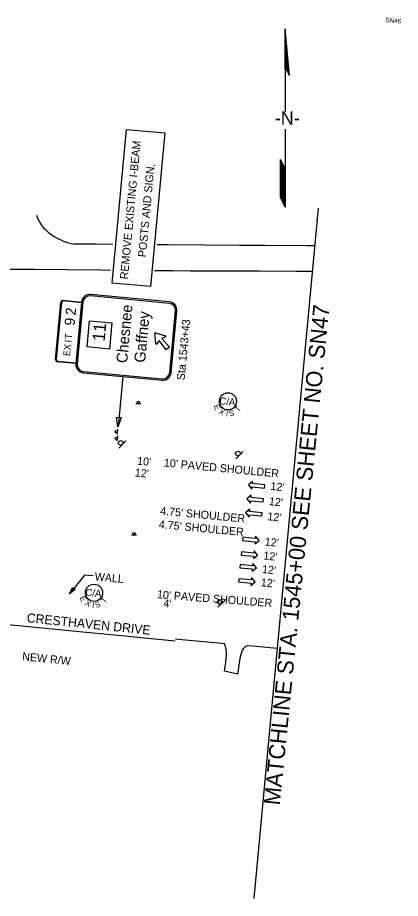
# Model space of a CAD drawing. Extents: x 1800374 to 1802004, y 1187708 to 1188617.
# Drawn here: x 1801669 to 1802004, y 1187708 to 1188479 of the extents above; entities that cross this region are included whole.
import ezdxf

# ---------------------------------------------------------------- set-up
doc = ezdxf.new("R2010")
doc.units = 0
for name, color, linetype in [('RD_EX_Road', 7, 'Continuous'), ('RD_PD_Final_LnLine', 7, 'Continuous'), ('RD_PD_Final_TX', 7, 'Continuous'), ('RD_PD_RW_TX', 7, 'Continuous'), ('RD_SHT_MatchLine', 7, 'Continuous'), ('RD_SHT_TX', 7, 'Continuous'), ('RD_Sketch1', 7, 'Continuous'), ('RD_Sketch8', 7, 'Continuous'), ('RD_TX_RoadID', 7, 'Continuous'), ('SN_P_Signs', 7, 'Continuous'), ('TERMINATOR', 7, 'Continuous')]:
    doc.layers.add(name, color=color, linetype=linetype)

# ---------------------------------------------------------------- blocks, each defined once
blk = doc.blocks.new('SARRW2')
at = {"layer": 'RD_PD_Final_LnLine'}
blk.add_lwpolyline([(-12, 1.2), (-12, -1.2), (-2.83, -1.2), (-2.83, -2.83), (0, 0), (-2.83, 2.83), (-2.83, 1.2)], close=True, dxfattribs=at)

msp = doc.modelspace()

# ---------------------------------------------------------------- linework, layer by layer
at = {"layer": 'RD_EX_Road'}
for points in [[(1801685.48, 1188305.79), (1801685.97, 1188304.34), (1801687.07, 1188301.79), (1801688.39, 1188299.35), (1801689.91, 1188297.02), (1801691.62, 1188294.84), (1801693.51, 1188292.81), (1801695.57, 1188290.95), (1801695.73, 1188290.82), (1801698.56, 1188288.7), (1801701.52, 1188286.79), (1801704.61, 1188285.07), (1801707.81, 1188283.57), (1801708.38, 1188283.32), (1801710.8, 1188282.35), (1801713.29, 1188281.6), (1801715.83, 1188281.08), (1801718.42, 1188280.79), (1801719.35, 1188280.74), (1801736.78, 1188280.71), (1801752.34, 1188280.54)], [(1801791.08, 1188280.16), (1801800.88, 1188280.08), (1801833.37, 1188279.84), (1801863.33, 1188279.56), (1801885.57, 1188279.5), (1801922.18, 1188279.21), (1801929.09, 1188279.22)], [(1801750.18, 1188257.47), (1801742.16, 1188257.54), (1801712.17, 1188257.84), (1801684.43, 1188258.15), (1801653.76, 1188258.34), (1801623.47, 1188258.55), (1801596.82, 1188258.7), (1801565.74, 1188258.88), (1801534.34, 1188259.2), (1801510.07, 1188259.36), (1801485.44, 1188259.54), (1801465.11, 1188259.51), (1801443.43, 1188259.67), (1801423.7, 1188259.6), (1801400.14, 1188259.52), (1801374.88, 1188259.49), (1801351.57, 1188259.44), (1801326.73, 1188259.43), (1801300.32, 1188259.52), (1801276.46, 1188259.35), (1801254.13, 1188259.2), (1801227.4, 1188259.14), (1801201, 1188258.95), (1801190.24, 1188258.95)], [(1801926.95, 1188256.38), (1801912.81, 1188256.45), (1801880.86, 1188256.7), (1801851.61, 1188256.8), (1801820.08, 1188256.94), (1801804.92, 1188257.1), (1801789.17, 1188257.21), (1801788.94, 1188257.21)], [(1801807.01, 1187933.22), (1801786, 1187935.24), (1801756.86, 1187938.09), (1801731.9, 1187940.55), (1801708.11, 1187942.83), (1801675.84, 1187945.99), (1801644.76, 1187948.86)], [(1801896.11, 1187926.73), (1801874.92, 1187928.81), (1801869.81, 1187929.15), (1801868.54, 1187928.39), (1801867.4, 1187927.44), (1801866.44, 1187926.32), (1801865.66, 1187925.06), (1801865.09, 1187923.69), (1801864.98, 1187923.33), (1801864.23, 1187920.71), (1801863.47, 1187918.08), (1801861.44, 1187904.4), (1801861.43, 1187904.32), (1801850.02, 1187906.92), (1801851.17, 1187914.64), (1801851.96, 1187920.9), (1801851.89, 1187923.45), (1801851.58, 1187925.99), (1801850.25, 1187930.85), (1801847.96, 1187931.07), (1801815.91, 1187934.08), (1801807.16, 1187934.81)]]:
    msp.add_lwpolyline(points, dxfattribs=at)
at = {"layer": 'RD_PD_Final_TX'}
for p, q in [((1801727.55, 1187990.9), (1801714.38, 1187974.42)), ((1801734.96, 1187990.21), (1801727.55, 1187990.9))]:
    msp.add_line(p, q, dxfattribs=at)
at = {"layer": 'RD_SHT_MatchLine'}
msp.add_line((1801932.15, 1188311.91), (1801875.67, 1187708.14), dxfattribs=at)
at = {"layer": 'RD_Sketch1'}
for p, q in [((1801903.25, 1188468.74), (1801903.04, 1188433.57)), ((1801906.98, 1188428.03), (1801903.25, 1188468.74)), ((1801903.55, 1188434.98), (1801906.98, 1188428.03)), ((1801903.25, 1188433.87), (1801903.25, 1188412.04)), ((1801903.25, 1188412.04), (1801903.25, 1188396.57)), ((1801903.25, 1188381.13), (1801903.25, 1188355.35)), ((1801899.26, 1188340.29), (1801899.26, 1188354.47)), ((1801899.26, 1188354.47), (1801903.25, 1188345.9)), ((1801903.25, 1188355.35), (1801903.25, 1188312.83)), ((1801899.26, 1188321.4), (1801899.26, 1188340.29)), ((1801903.25, 1188312.83), (1801899.26, 1188321.4))]:
    msp.add_line(p, q, dxfattribs=at)
for points in [[(1801903.26, 1188434.18), (1801903.26, 1188468.62)], [(1801903.36, 1188434.44), (1801903.36, 1188467.58)], [(1801903.45, 1188434.7), (1801903.45, 1188466.55)], [(1801903.55, 1188434.95), (1801903.55, 1188465.52)], [(1801903.64, 1188434.8), (1801903.64, 1188464.49)], [(1801903.74, 1188434.61), (1801903.74, 1188463.45)], [(1801903.83, 1188434.42), (1801903.83, 1188462.42)], [(1801903.92, 1188434.23), (1801903.92, 1188461.39)], [(1801904.02, 1188434.04), (1801904.02, 1188460.36)], [(1801904.11, 1188433.84), (1801904.11, 1188459.32)], [(1801904.21, 1188433.65), (1801904.21, 1188458.29)], [(1801903.17, 1188433.92), (1801903.17, 1188454.7)], [(1801904.3, 1188433.46), (1801904.3, 1188457.26)], [(1801904.4, 1188433.27), (1801904.4, 1188456.23)], [(1801904.49, 1188433.08), (1801904.49, 1188455.19)], [(1801904.59, 1188432.89), (1801904.59, 1188454.16)], [(1801904.68, 1188432.69), (1801904.68, 1188453.13)], [(1801904.77, 1188432.5), (1801904.77, 1188452.1)], [(1801904.87, 1188432.31), (1801904.87, 1188451.06)], [(1801904.96, 1188432.12), (1801904.96, 1188450.03)], [(1801905.06, 1188431.93), (1801905.06, 1188449)], [(1801905.15, 1188431.74), (1801905.15, 1188447.97)], [(1801905.25, 1188431.54), (1801905.25, 1188446.93)], [(1801905.34, 1188431.35), (1801905.34, 1188445.9)], [(1801905.44, 1188431.16), (1801905.44, 1188444.87)], [(1801905.53, 1188430.97), (1801905.53, 1188443.84)], [(1801905.62, 1188430.78), (1801905.62, 1188442.8)], [(1801903.07, 1188433.66), (1801903.07, 1188438.8)], [(1801905.72, 1188430.58), (1801905.72, 1188441.77)], [(1801905.81, 1188430.39), (1801905.81, 1188440.74)], [(1801905.91, 1188430.2), (1801905.91, 1188439.71)], [(1801906, 1188430.01), (1801906, 1188438.67)], [(1801906.1, 1188429.82), (1801906.1, 1188437.64)], [(1801906.19, 1188429.63), (1801906.19, 1188436.61)], [(1801906.29, 1188429.43), (1801906.29, 1188435.58)], [(1801906.38, 1188429.24), (1801906.38, 1188434.54)], [(1801906.48, 1188429.05), (1801906.48, 1188433.51)], [(1801906.57, 1188428.86), (1801906.57, 1188432.48)], [(1801906.66, 1188428.67), (1801906.66, 1188431.45)], [(1801906.76, 1188428.48), (1801906.76, 1188430.41)], [(1801906.85, 1188428.28), (1801906.85, 1188429.38)], [(1801906.95, 1188428.09), (1801906.95, 1188428.35)], [(1801899.34, 1188321.23), (1801899.34, 1188354.3)], [(1801899.43, 1188321.03), (1801899.43, 1188354.1)], [(1801899.52, 1188320.83), (1801899.52, 1188353.9)], [(1801899.62, 1188320.62), (1801899.62, 1188353.69)], [(1801899.71, 1188320.42), (1801899.71, 1188353.49)], [(1801899.81, 1188320.22), (1801899.81, 1188353.29)], [(1801899.9, 1188320.01), (1801899.9, 1188353.09)], [(1801900, 1188319.81), (1801900, 1188352.88)], [(1801900.09, 1188319.61), (1801900.09, 1188352.68)], [(1801900.19, 1188319.41), (1801900.19, 1188352.48)], [(1801900.28, 1188319.2), (1801900.28, 1188352.27)], [(1801900.37, 1188319), (1801900.37, 1188352.07)], [(1801900.47, 1188318.8), (1801900.47, 1188351.87)], [(1801900.56, 1188318.6), (1801900.56, 1188351.67)], [(1801900.66, 1188318.39), (1801900.66, 1188351.46)], [(1801900.75, 1188318.19), (1801900.75, 1188351.26)], [(1801900.85, 1188317.99), (1801900.85, 1188351.06)], [(1801900.94, 1188317.79), (1801900.94, 1188350.86)], [(1801901.04, 1188317.58), (1801901.04, 1188350.65)], [(1801901.13, 1188317.38), (1801901.13, 1188350.45)], [(1801901.22, 1188317.18), (1801901.22, 1188350.25)], [(1801901.32, 1188316.98), (1801901.32, 1188350.05)], [(1801901.41, 1188316.77), (1801901.41, 1188349.84)], [(1801901.51, 1188316.57), (1801901.51, 1188349.64)], [(1801901.6, 1188316.37), (1801901.6, 1188349.44)], [(1801901.7, 1188316.16), (1801901.7, 1188349.24)], [(1801901.79, 1188315.96), (1801901.79, 1188349.03)], [(1801901.89, 1188315.76), (1801901.89, 1188348.83)], [(1801901.98, 1188315.56), (1801901.98, 1188348.63)], [(1801902.08, 1188315.35), (1801902.08, 1188348.42)], [(1801902.17, 1188315.15), (1801902.17, 1188348.22)], [(1801902.26, 1188314.95), (1801902.26, 1188348.02)], [(1801902.36, 1188314.75), (1801902.36, 1188347.82)], [(1801902.45, 1188314.54), (1801902.45, 1188347.61)], [(1801902.55, 1188314.34), (1801902.55, 1188347.41)], [(1801902.64, 1188314.14), (1801902.64, 1188347.21)], [(1801902.74, 1188313.94), (1801902.74, 1188347.01)], [(1801902.83, 1188313.73), (1801902.83, 1188346.8)], [(1801902.93, 1188313.53), (1801902.93, 1188346.6)], [(1801903.02, 1188313.33), (1801903.02, 1188346.4)], [(1801903.11, 1188313.13), (1801903.11, 1188346.2)], [(1801903.21, 1188312.92), (1801903.21, 1188345.99)]]:
    msp.add_lwpolyline(points, dxfattribs=at)
at = {"layer": 'RD_Sketch8'}
for centre in [(1801853.07, 1188142.95), (1801735.87, 1187975.47)]:
    msp.add_circle(centre, 7.5, dxfattribs=at)
at = {"layer": 'SN_P_Signs'}
for p, q in [((1801751.74, 1188246.41), (1801764.32, 1188380.84)), ((1801764.32, 1188380.84), (1801797.79, 1188377.71)), ((1801797.79, 1188377.71), (1801785.21, 1188243.28)), ((1801785.21, 1188243.28), (1801751.74, 1188246.41)), ((1801801.82, 1188228.65), (1801732.71, 1188235.11)), ((1801731.89, 1188213.47), (1801751.49, 1188211.64)), ((1801751.49, 1188211.64), (1801749.34, 1188188.67)), ((1801749.34, 1188188.67), (1801729.74, 1188190.5)), ((1801726.54, 1188169.08), (1801795.64, 1188162.62)), ((1801760.98, 1188164.66), (1801756.86, 1188120.71)), ((1801772.37, 1188140.99), (1801776.87, 1188140.99)), ((1801756.16, 1188114.03), (1801756.57, 1188118.51)), ((1801756.25, 1188108.25), (1801756.67, 1188112.73)), ((1801757.43, 1188102.02), (1801763.79, 1188108.38)), ((1801860.09, 1188092.7), (1801866.45, 1188099.07)), ((1801768.55, 1188026.26), (1801773.05, 1188026.26)), ((1801844.29, 1187962.74), (1801850.65, 1187969.11))]:
    msp.add_line(p, q, dxfattribs=at)
for points in [[(1801801.93, 1188229.84), (1801732.83, 1188236.31)], [(1801702.2, 1188179.51), (1801706.9, 1188229.69)], [(1801707.49, 1188229.64), (1801702.8, 1188179.46)], [(1801724.93, 1188229.21), (1801708.8, 1188230.72)], [(1801708.86, 1188231.32), (1801724.99, 1188229.81), (1801724.93, 1188229.21)], [(1801724.99, 1188229.81), (1801719.93, 1188175.73)], [(1801726.18, 1188229.7), (1801721.12, 1188175.62)], [(1801802.17, 1188168.03), (1801807.23, 1188222.12)], [(1801803.37, 1188167.92), (1801808.43, 1188222)], [(1801729.74, 1188190.5), (1801731.89, 1188213.47)], [(1801790.02, 1188193.38), (1801789.11, 1188202.36)], [(1801789.68, 1188202.84), (1801798.34, 1188200.27)], [(1801793.01, 1188196.11), (1801790.83, 1188193.16)], [(1801801.85, 1188190.39), (1801799.08, 1188188.09), (1801793.01, 1188196.11)], [(1801798.4, 1188199.43), (1801795.09, 1188197.84)], [(1801795.09, 1188197.84), (1801801.85, 1188190.39)], [(1801703.88, 1188178.15), (1801720.01, 1188176.64), (1801719.96, 1188176.04), (1801703.83, 1188177.55)], [(1801726.42, 1188167.89), (1801795.53, 1188161.42)]]:
    msp.add_lwpolyline(points, dxfattribs=at)
msp.add_lwpolyline([(1801759.54, 1188128.72), (1801756.82, 1188120.72), (1801755.45, 1188129.06)], close=True, dxfattribs=at)
for centre, radius in [((1801774.63, 1188142), 1), ((1801755.36, 1188116.37), 1), ((1801755.45, 1188110.59), 1), ((1801759.19, 1188106.65), 2), ((1801861.85, 1188097.33), 2), ((1801770.81, 1188027.28), 1), ((1801846.05, 1187967.37), 2)]:
    msp.add_circle(centre, radius, dxfattribs=at)
for centre, radius, start, end in [((1801732.15, 1188229.14), 7.2, 84.65568, 174.65568), ((1801732.15, 1188229.14), 6, 84.65568, 174.65568), ((1801708.69, 1188229.53), 1.8, 84.65568, 174.65568), ((1801708.69, 1188229.53), 1.2, 84.65568, 174.65568), ((1801801.26, 1188222.67), 6, 354.65568, 84.65568), ((1801801.26, 1188222.67), 7.2, 354.65568, 84.65568), ((1801789.55, 1188202.4), 0.45, 73.47778, 185.83358), ((1801798.21, 1188199.84), 0.45, 295.69358, 73.47778), ((1801790.47, 1188193.42), 0.45, 185.83358, 323.61778), ((1801703.99, 1188179.35), 1.8, 174.65568, 264.65568), ((1801703.99, 1188179.35), 1.2, 174.65568, 264.65568), ((1801727.1, 1188175.06), 7.2, 174.65568, 264.65568), ((1801727.1, 1188175.06), 6, 174.65568, 264.65568), ((1801796.2, 1188168.59), 7.2, 264.65568, 354.65568), ((1801796.2, 1188168.59), 6, 264.65568, 354.65568)]:
    msp.add_arc(centre, radius, start, end, dxfattribs=at)
at = {"layer": 'TERMINATOR'}
msp.add_lwpolyline([(1801719.33, 1187978.23), (1801714.42, 1187974.48), (1801716.99, 1187980.11)], close=True, dxfattribs=at)

# ---------------------------------------------------------------- block references
at = {"layer": 'RD_PD_Final_LnLine'}
for p, xscale, yscale, rotation in [((1801870.99, 1188069.87), 1.1999999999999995, 1.200000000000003, 174.65567699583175), ((1801869.78, 1188057.65), 1.1999999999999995, 1.200000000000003, 174.65567699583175), ((1801868.57, 1188045.42), 1.1999999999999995, 1.200000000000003, 174.65567699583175), ((1801880.34, 1188021.23), 1.1999999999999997, 1.2000000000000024, -5.34432300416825), ((1801879.08, 1188008.51), 1.1999999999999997, 1.2000000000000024, -5.34432300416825), ((1801877.97, 1187997.4), 1.1999999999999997, 1.2000000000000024, -5.34432300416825), ((1801876.81, 1187985.02), 1.1999999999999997, 1.2000000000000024, -5.34432300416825)]:
    msp.add_blockref('SARRW2', p, dxfattribs=dict(at, xscale=xscale, yscale=yscale, rotation=rotation))

# ---------------------------------------------------------------- texts
at = {"layer": 'RD_PD_Final_TX'}
for s, rotation, p in [("10'", 354.76418, (1801773.34, 1188087.55)), ("10' PAVED SHOULDER", 354.54177, (1801796.75, 1188085.92)), ("12'", 354.76418, (1801771.36, 1188077.25)), ("12'", 354.02886, (1801890.03, 1188065.5)), ("12'", 353.95121, (1801888.72, 1188052.22)), ("4.75' SHOULDER", 354.65568, (1801793.53, 1188043.83)), ("12'", 354.02886, (1801887.41, 1188039.01)), ("4.75' SHOULDER", 354.65568, (1801792.32, 1188032.08)), ("12'", 353.95121, (1801885.07, 1188016.93)), ("12'", 353.95121, (1801883.85, 1188004.72)), ("12'", 353.95121, (1801882.67, 1187992.84)), ('WALL', 354.65568, (1801736.2, 1187986.35)), ("12'", 353.95121, (1801881.59, 1187981.26)), ("10' PAVED SHOULDER", 355.58396, (1801790.77, 1187970.72)), ("4'", 354.76418, (1801796.32, 1187962.93))]:
    msp.add_text(s, height=7, rotation=rotation, dxfattribs=at).set_placement(p)
at = {"layer": 'RD_PD_RW_TX'}
msp.add_text('NEW R/W', height=7, rotation=354.20316, dxfattribs=at).set_placement((1801672.68, 1187916.48))
at = {"layer": 'RD_SHT_TX'}
for s, height, rotation, p in [('SN46', 4, 354.65567, (1801990.82, 1188474.66)), ('MATCHLINE STA. 1545+00 SEE SHEET NO. SN47', 14.1726, 84.31294, (1801898.54, 1187789.14))]:
    msp.add_text(s, height=height, rotation=rotation, dxfattribs=at).set_placement(p)
at = {"layer": 'RD_Sketch1'}
msp.add_text('-N-', height=11.811, rotation=0, dxfattribs=at).set_placement((1801894.06, 1188384.84))
at = {"layer": 'RD_Sketch8'}
for s, height, rotation, p in [('C/A', 6.25, 354.65568, (1801845.38, 1188140.38)), ('E', 5, 297.86692, (1801840.39, 1188138.59)), ('X', 5, 330.29629, (1801844.62, 1188132.52)), ('I', 5, 354.45629, (1801851.18, 1188129.82)), ('S', 5, 16.44812, (1801854.83, 1188129.66)), ('T', 5, 52.84082, (1801862.4, 1188133.33)), ('E', 5, 297.86692, (1801723.18, 1187971.11)), ('C/A', 6.25, 354.65568, (1801728.18, 1187972.9)), ('T', 5, 52.84082, (1801745.2, 1187965.85)), ('X', 5, 330.29629, (1801727.42, 1187965.04)), ('I', 5, 354.45629, (1801733.98, 1187962.34)), ('S', 5, 16.44812, (1801737.63, 1187962.18))]:
    msp.add_text(s, height=height, rotation=rotation, dxfattribs=at).set_placement(p)
at = {"layer": 'RD_TX_RoadID'}
msp.add_text('CRESTHAVEN DRIVE', height=8, rotation=354.16078, dxfattribs=at).set_placement((1801676.73, 1187949.76))
at = {"layer": 'SN_P_Signs'}
for s, height, rotation, p in [('REMOVE EXISTING I-BEAM', 6.9998, 84.65576, (1801765.45, 1188249.44)), ('POSTS AND SIGN.', 6.9998, 84.65576, (1801781.31, 1188268.75)), ('Chesnee', 9.6, 84.65568, (1801764.85, 1188176.05)), ('2', 9, 84.65568, (1801719.65, 1188217.91)), ('Gaffney', 9.6, 84.65568, (1801780.52, 1188176.42)), ('9', 9, 84.65568, (1801718.81, 1188208.85)), ('Sta 1543+43', 7, 84.65576, (1801815.16, 1188161.18)), ('11', 10.8, 84.65568, (1801745.09, 1188195.12)), ('I', 6, 84.65568, (1801715.93, 1188194.2)), ('T', 6, 84.65568, (1801716.21, 1188197.17)), ('E', 6, 84.65568, (1801714.82, 1188182.28)), ('X', 6, 84.65568, (1801715.3, 1188187.41))]:
    msp.add_text(s, height=height, rotation=rotation, dxfattribs=at).set_placement(p)

doc.saveas('drawing.dxf')
